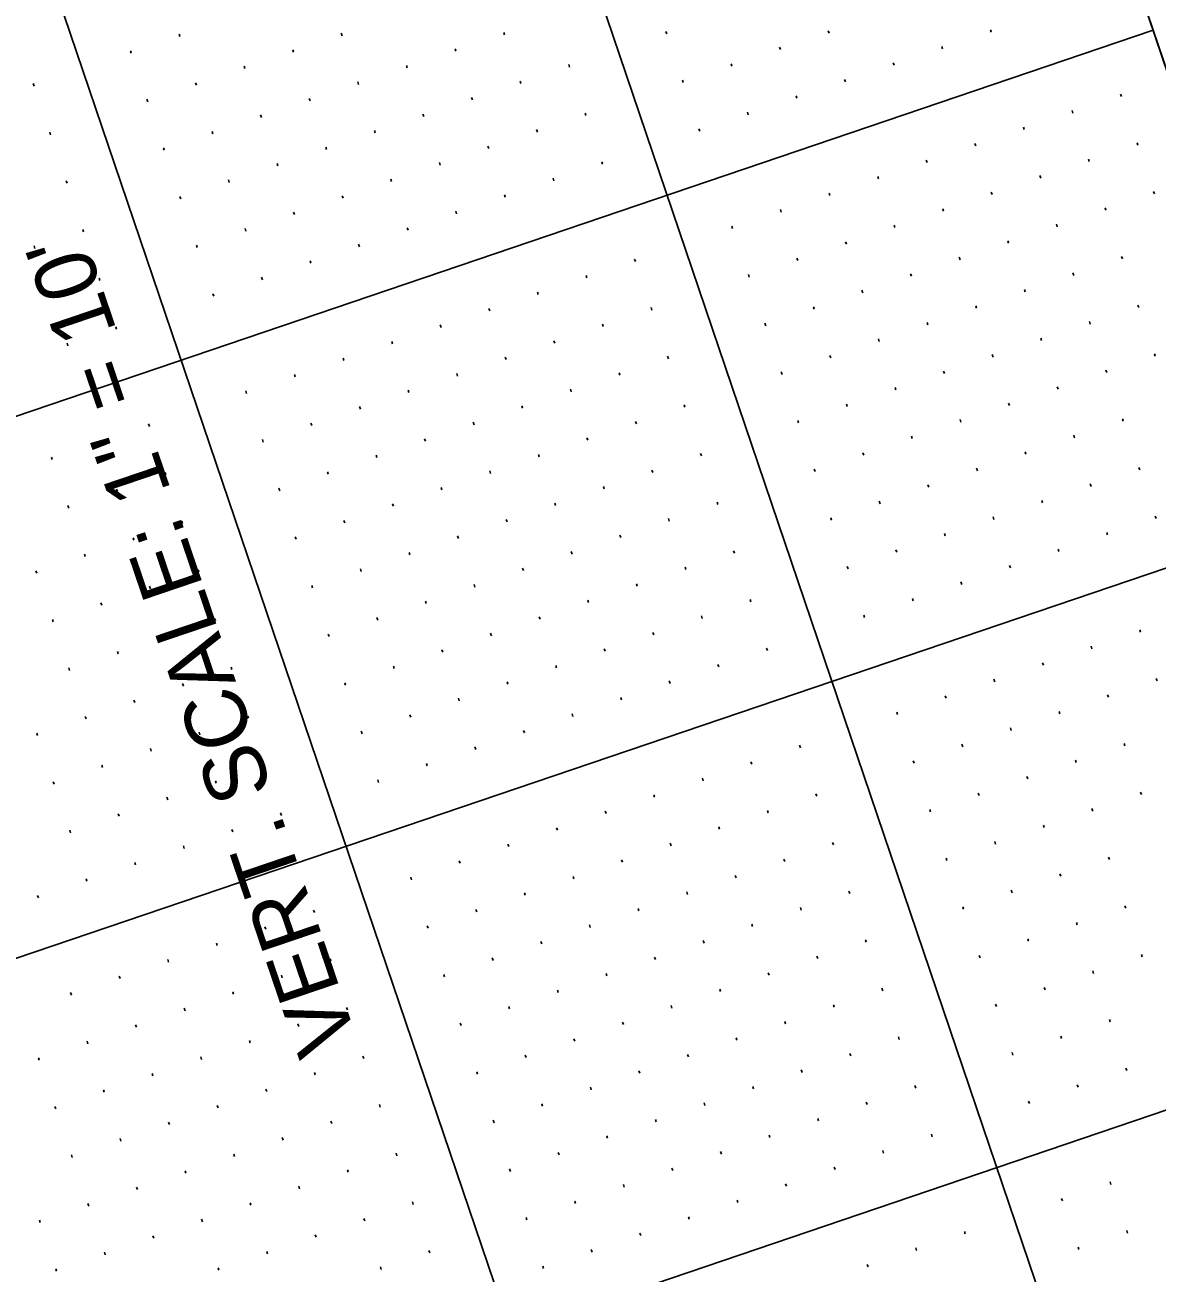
# Model space of a CAD drawing. Extents: x 2150800 to 2152547, y 141860 to 143950.
# Drawn here: x 2151679 to 2151789.3, y 143638.5 to 143760 of the extents above; entities that cross this region are included whole.
import ezdxf

# ---------------------------------------------------------------- set-up
doc = ezdxf.new("R2010")
doc.units = 0
for name, color, linetype in [('SHT_Profile_Grid_Major', 7, 'Continuous'), ('SHT_Profile_Grid_Minor', 7, 'Continuous'), ('SHT_Scale', 7, 'Continuous'), ('SHT_Sheet_Border', 7, 'Continuous')]:
    doc.layers.add(name, color=color, linetype=linetype)

msp = doc.modelspace()

# ---------------------------------------------------------------- linework, layer by layer
at = {"layer": 'SHT_Profile_Grid_Major'}
for p, q in [((2152266.81, 142350.86), (2151760.82, 143842.37)), ((2152219.46, 142334.8), (2151713.47, 143826.31)), ((2152172.11, 142318.73), (2151666.12, 143810.24)), ((2151788.93, 143759.51), (2151452.75, 143645.46)), ((2151804.99, 143712.16), (2151468.81, 143598.11)), ((2151892.08, 143688.9), (2151484.88, 143550.76))]:
    msp.add_line(p, q, dxfattribs=at)
at = {"layer": 'SHT_Profile_Grid_Minor'}
for p, q in [((2151694.1, 143758.88), (2151694.02, 143759.12)), ((2151709.91, 143758.97), (2151709.83, 143759.21)), ((2151725.73, 143759.05), (2151725.65, 143759.29)), ((2151741.54, 143759.14), (2151741.46, 143759.37)), ((2151757.35, 143759.22), (2151757.27, 143759.46)), ((2151773.16, 143759.3), (2151773.08, 143759.54)), ((2151752.61, 143757.61), (2151752.53, 143757.85)), ((2151768.42, 143757.7), (2151768.34, 143757.93)), ((2151689.37, 143757.28), (2151689.29, 143757.51)), ((2151705.18, 143757.36), (2151705.1, 143757.6)), ((2151720.99, 143757.45), (2151720.91, 143757.68)), ((2151700.44, 143755.76), (2151700.36, 143755.99)), ((2151716.26, 143755.84), (2151716.18, 143756.08)), ((2151732.07, 143755.92), (2151731.99, 143756.16)), ((2151747.88, 143756.01), (2151747.8, 143756.24)), ((2151763.69, 143756.09), (2151763.61, 143756.33)), ((2151679.9, 143754.07), (2151679.82, 143754.3)), ((2151695.71, 143754.15), (2151695.63, 143754.39)), ((2151711.52, 143754.23), (2151711.44, 143754.47)), ((2151727.33, 143754.32), (2151727.25, 143754.55)), ((2151743.14, 143754.4), (2151743.06, 143754.64)), ((2151758.95, 143754.49), (2151758.87, 143754.72)), ((2151754.22, 143752.88), (2151754.14, 143753.12)), ((2151785.84, 143753.05), (2151785.76, 143753.28)), ((2151690.98, 143752.54), (2151690.89, 143752.78)), ((2151706.79, 143752.63), (2151706.71, 143752.86)), ((2151722.6, 143752.71), (2151722.52, 143752.95)), ((2151702.05, 143751.02), (2151701.97, 143751.26)), ((2151717.86, 143751.1), (2151717.78, 143751.34)), ((2151733.67, 143751.19), (2151733.59, 143751.43)), ((2151749.48, 143751.27), (2151749.4, 143751.51)), ((2151781.11, 143751.44), (2151781.03, 143751.68)), ((2151681.51, 143749.33), (2151681.42, 143749.57)), ((2151697.32, 143749.41), (2151697.24, 143749.65)), ((2151713.13, 143749.5), (2151713.05, 143749.74)), ((2151728.94, 143749.58), (2151728.86, 143749.82)), ((2151744.75, 143749.67), (2151744.67, 143749.9)), ((2151776.37, 143749.83), (2151776.29, 143750.07)), ((2151708.39, 143747.89), (2151708.31, 143748.13)), ((2151724.2, 143747.98), (2151724.12, 143748.21)), ((2151771.64, 143748.23), (2151771.56, 143748.46)), ((2151787.45, 143748.31), (2151787.37, 143748.55)), ((2151692.58, 143747.81), (2151692.5, 143748.04)), ((2151782.71, 143746.71), (2151782.63, 143746.94)), ((2151703.66, 143746.29), (2151703.58, 143746.52)), ((2151719.47, 143746.37), (2151719.39, 143746.61)), ((2151735.28, 143746.45), (2151735.2, 143746.69)), ((2151766.9, 143746.62), (2151766.82, 143746.86)), ((2151683.11, 143744.6), (2151683.03, 143744.83)), ((2151698.92, 143744.68), (2151698.84, 143744.92)), ((2151714.73, 143744.76), (2151714.65, 143745)), ((2151730.54, 143744.85), (2151730.46, 143745.08)), ((2151762.17, 143745.02), (2151762.09, 143745.25)), ((2151777.98, 143745.1), (2151777.9, 143745.34)), ((2151694.19, 143743.07), (2151694.11, 143743.31)), ((2151710, 143743.16), (2151709.92, 143743.39)), ((2151725.81, 143743.24), (2151725.73, 143743.48)), ((2151757.43, 143743.41), (2151757.35, 143743.65)), ((2151773.24, 143743.49), (2151773.16, 143743.73)), ((2151789.05, 143743.58), (2151788.97, 143743.81)), ((2151752.7, 143741.8), (2151752.62, 143742.04)), ((2151768.51, 143741.89), (2151768.43, 143742.12)), ((2151784.32, 143741.97), (2151784.24, 143742.21)), ((2151705.26, 143741.55), (2151705.18, 143741.79)), ((2151721.07, 143741.63), (2151720.99, 143741.87)), ((2151684.72, 143739.86), (2151684.64, 143740.1)), ((2151700.53, 143739.94), (2151700.45, 143740.18)), ((2151716.34, 143740.03), (2151716.26, 143740.27)), ((2151747.96, 143740.2), (2151747.88, 143740.43)), ((2151763.77, 143740.28), (2151763.69, 143740.52)), ((2151779.58, 143740.36), (2151779.5, 143740.6)), ((2151679.98, 143738.25), (2151679.9, 143738.49)), ((2151695.79, 143738.34), (2151695.71, 143738.57)), ((2151711.61, 143738.42), (2151711.52, 143738.66)), ((2151759.04, 143738.67), (2151758.96, 143738.91)), ((2151774.85, 143738.76), (2151774.77, 143738.99)), ((2151738.49, 143736.98), (2151738.41, 143737.22)), ((2151754.3, 143737.07), (2151754.22, 143737.3)), ((2151770.11, 143737.15), (2151770.03, 143737.39)), ((2151785.93, 143737.24), (2151785.85, 143737.47)), ((2151706.87, 143736.82), (2151706.79, 143737.05)), ((2151686.32, 143735.13), (2151686.24, 143735.36)), ((2151702.14, 143735.21), (2151702.05, 143735.45)), ((2151733.76, 143735.38), (2151733.68, 143735.61)), ((2151749.57, 143735.46), (2151749.49, 143735.7)), ((2151765.38, 143735.55), (2151765.3, 143735.78)), ((2151781.19, 143735.63), (2151781.11, 143735.87)), ((2151681.59, 143733.52), (2151681.51, 143733.76)), ((2151697.4, 143733.6), (2151697.32, 143733.84)), ((2151729.02, 143733.77), (2151728.94, 143734.01)), ((2151760.64, 143733.94), (2151760.56, 143734.18)), ((2151776.46, 143734.02), (2151776.38, 143734.26)), ((2151724.29, 143732.16), (2151724.21, 143732.4)), ((2151740.1, 143732.25), (2151740.02, 143732.49)), ((2151755.91, 143732.33), (2151755.83, 143732.57)), ((2151771.72, 143732.42), (2151771.64, 143732.65)), ((2151787.53, 143732.5), (2151787.45, 143732.74)), ((2151782.8, 143730.89), (2151782.72, 143731.13)), ((2151687.93, 143730.39), (2151687.85, 143730.63)), ((2151719.55, 143730.56), (2151719.47, 143730.8)), ((2151735.36, 143730.64), (2151735.28, 143730.88)), ((2151751.18, 143730.73), (2151751.09, 143730.96)), ((2151766.99, 143730.81), (2151766.91, 143731.05)), ((2151683.2, 143728.78), (2151683.12, 143729.02)), ((2151714.82, 143728.95), (2151714.74, 143729.19)), ((2151730.63, 143729.04), (2151730.55, 143729.27)), ((2151762.25, 143729.2), (2151762.17, 143729.44)), ((2151778.06, 143729.29), (2151777.98, 143729.53)), ((2151710.08, 143727.35), (2151710, 143727.58)), ((2151725.89, 143727.43), (2151725.81, 143727.67)), ((2151741.71, 143727.51), (2151741.62, 143727.75)), ((2151757.52, 143727.6), (2151757.44, 143727.83)), ((2151773.33, 143727.68), (2151773.25, 143727.92)), ((2151789.14, 143727.77), (2151789.06, 143728)), ((2151752.78, 143725.99), (2151752.7, 143726.23)), ((2151768.59, 143726.08), (2151768.51, 143726.31)), ((2151784.4, 143726.16), (2151784.32, 143726.4)), ((2151705.35, 143725.74), (2151705.27, 143725.98)), ((2151721.16, 143725.82), (2151721.08, 143726.06)), ((2151736.97, 143725.91), (2151736.89, 143726.14)), ((2151700.61, 143724.13), (2151700.53, 143724.37)), ((2151716.42, 143724.22), (2151716.34, 143724.45)), ((2151732.24, 143724.3), (2151732.15, 143724.54)), ((2151763.86, 143724.47), (2151763.78, 143724.71)), ((2151779.67, 143724.55), (2151779.59, 143724.79)), ((2151711.69, 143722.61), (2151711.61, 143722.85)), ((2151727.5, 143722.7), (2151727.42, 143722.93)), ((2151743.31, 143722.78), (2151743.23, 143723.02)), ((2151759.12, 143722.86), (2151759.04, 143723.1)), ((2151774.93, 143722.95), (2151774.85, 143723.18)), ((2151738.58, 143721.17), (2151738.5, 143721.41)), ((2151754.39, 143721.26), (2151754.31, 143721.49)), ((2151770.2, 143721.34), (2151770.12, 143721.58)), ((2151786.01, 143721.42), (2151785.93, 143721.66)), ((2151691.14, 143720.92), (2151691.06, 143721.16)), ((2151706.95, 143721), (2151706.87, 143721.24)), ((2151722.77, 143721.09), (2151722.69, 143721.33)), ((2151686.41, 143719.31), (2151686.33, 143719.55)), ((2151702.22, 143719.4), (2151702.14, 143719.64)), ((2151718.03, 143719.48), (2151717.95, 143719.72)), ((2151733.84, 143719.57), (2151733.76, 143719.8)), ((2151765.46, 143719.73), (2151765.38, 143719.97)), ((2151781.28, 143719.82), (2151781.19, 143720.06)), ((2151681.67, 143717.71), (2151681.59, 143717.94)), ((2151713.3, 143717.88), (2151713.22, 143718.11)), ((2151729.11, 143717.96), (2151729.03, 143718.2)), ((2151744.92, 143718.04), (2151744.84, 143718.28)), ((2151760.73, 143718.13), (2151760.65, 143718.36)), ((2151776.54, 143718.21), (2151776.46, 143718.45)), ((2151708.56, 143716.27), (2151708.48, 143716.51)), ((2151724.37, 143716.35), (2151724.29, 143716.59)), ((2151740.18, 143716.44), (2151740.1, 143716.67)), ((2151755.99, 143716.52), (2151755.91, 143716.76)), ((2151771.81, 143716.61), (2151771.72, 143716.84)), ((2151787.62, 143716.69), (2151787.54, 143716.93)), ((2151692.75, 143716.19), (2151692.67, 143716.42)), ((2151782.88, 143715.08), (2151782.8, 143715.32)), ((2151688.01, 143714.58), (2151687.93, 143714.82)), ((2151703.83, 143714.66), (2151703.75, 143714.9)), ((2151719.64, 143714.75), (2151719.56, 143714.98)), ((2151735.45, 143714.83), (2151735.37, 143715.07)), ((2151767.07, 143715), (2151766.99, 143715.24)), ((2151683.28, 143712.97), (2151683.2, 143713.21)), ((2151714.9, 143713.14), (2151714.82, 143713.38)), ((2151730.71, 143713.23), (2151730.63, 143713.46)), ((2151746.52, 143713.31), (2151746.44, 143713.55)), ((2151762.34, 143713.39), (2151762.25, 143713.63)), ((2151778.15, 143713.48), (2151778.07, 143713.71)), ((2151694.36, 143711.45), (2151694.28, 143711.69)), ((2151710.17, 143711.53), (2151710.09, 143711.77)), ((2151725.98, 143711.62), (2151725.9, 143711.86)), ((2151741.79, 143711.7), (2151741.71, 143711.94)), ((2151757.6, 143711.79), (2151757.52, 143712.02)), ((2151773.41, 143711.87), (2151773.33, 143712.11)), ((2151789.22, 143711.95), (2151789.14, 143712.19)), ((2151768.68, 143710.26), (2151768.6, 143710.5)), ((2151784.49, 143710.35), (2151784.41, 143710.59)), ((2151689.62, 143709.84), (2151689.54, 143710.08)), ((2151705.43, 143709.93), (2151705.35, 143710.17)), ((2151721.24, 143710.01), (2151721.16, 143710.25)), ((2151737.05, 143710.1), (2151736.97, 143710.33)), ((2151684.89, 143708.24), (2151684.81, 143708.47)), ((2151716.51, 143708.41), (2151716.43, 143708.64)), ((2151732.32, 143708.49), (2151732.24, 143708.73)), ((2151748.13, 143708.57), (2151748.05, 143708.81)), ((2151763.94, 143708.66), (2151763.86, 143708.89)), ((2151779.75, 143708.74), (2151779.67, 143708.98)), ((2151680.15, 143706.63), (2151680.07, 143706.87)), ((2151695.96, 143706.72), (2151695.88, 143706.95)), ((2151711.77, 143706.8), (2151711.69, 143707.04)), ((2151727.58, 143706.88), (2151727.5, 143707.12)), ((2151743.4, 143706.97), (2151743.32, 143707.2)), ((2151759.21, 143707.05), (2151759.13, 143707.29)), ((2151775.02, 143707.14), (2151774.94, 143707.37)), ((2151738.66, 143705.36), (2151738.58, 143705.6)), ((2151770.28, 143705.53), (2151770.2, 143705.77)), ((2151691.23, 143705.11), (2151691.15, 143705.35)), ((2151707.04, 143705.19), (2151706.96, 143705.43)), ((2151722.85, 143705.28), (2151722.77, 143705.51)), ((2151686.49, 143703.5), (2151686.41, 143703.74)), ((2151718.11, 143703.67), (2151718.03, 143703.91)), ((2151733.93, 143703.76), (2151733.85, 143703.99)), ((2151749.74, 143703.84), (2151749.66, 143704.08)), ((2151765.55, 143703.92), (2151765.47, 143704.16)), ((2151681.76, 143701.9), (2151681.68, 143702.13)), ((2151697.57, 143701.98), (2151697.49, 143702.22)), ((2151713.38, 143702.06), (2151713.3, 143702.3)), ((2151729.19, 143702.15), (2151729.11, 143702.39)), ((2151745, 143702.23), (2151744.92, 143702.47)), ((2151760.81, 143702.32), (2151760.73, 143702.55)), ((2151708.64, 143700.46), (2151708.56, 143700.7)), ((2151724.46, 143700.54), (2151724.38, 143700.78)), ((2151740.27, 143700.63), (2151740.19, 143700.86)), ((2151787.7, 143700.88), (2151787.62, 143701.12)), ((2151692.83, 143700.37), (2151692.75, 143700.61)), ((2151782.97, 143699.27), (2151782.89, 143699.51)), ((2151688.1, 143698.77), (2151688.02, 143699.01)), ((2151719.72, 143698.94), (2151719.64, 143699.17)), ((2151735.53, 143699.02), (2151735.45, 143699.26)), ((2151751.34, 143699.1), (2151751.26, 143699.34)), ((2151683.36, 143697.16), (2151683.28, 143697.4)), ((2151699.17, 143697.25), (2151699.09, 143697.48)), ((2151714.99, 143697.33), (2151714.91, 143697.57)), ((2151730.8, 143697.41), (2151730.72, 143697.65)), ((2151746.61, 143697.5), (2151746.53, 143697.73)), ((2151778.23, 143697.67), (2151778.15, 143697.9)), ((2151694.44, 143695.64), (2151694.36, 143695.88)), ((2151710.25, 143695.72), (2151710.17, 143695.96)), ((2151726.06, 143695.81), (2151725.98, 143696.04)), ((2151741.87, 143695.89), (2151741.79, 143696.13)), ((2151773.5, 143696.06), (2151773.42, 143696.3)), ((2151789.31, 143696.14), (2151789.23, 143696.38)), ((2151768.76, 143694.45), (2151768.68, 143694.69)), ((2151784.57, 143694.54), (2151784.49, 143694.77)), ((2151689.7, 143694.03), (2151689.62, 143694.27)), ((2151721.33, 143694.2), (2151721.25, 143694.44)), ((2151737.14, 143694.29), (2151737.06, 143694.52)), ((2151684.97, 143692.43), (2151684.89, 143692.66)), ((2151700.78, 143692.51), (2151700.7, 143692.75)), ((2151716.59, 143692.6), (2151716.51, 143692.83)), ((2151732.4, 143692.68), (2151732.32, 143692.92)), ((2151764.03, 143692.85), (2151763.95, 143693.08)), ((2151779.84, 143692.93), (2151779.76, 143693.17)), ((2151680.23, 143690.82), (2151680.15, 143691.06)), ((2151696.05, 143690.9), (2151695.97, 143691.14)), ((2151711.86, 143690.99), (2151711.78, 143691.23)), ((2151727.67, 143691.07), (2151727.59, 143691.31)), ((2151775.1, 143691.32), (2151775.02, 143691.56)), ((2151754.56, 143689.63), (2151754.48, 143689.87)), ((2151770.37, 143689.72), (2151770.29, 143689.96)), ((2151786.18, 143689.8), (2151786.1, 143690.04)), ((2151691.31, 143689.3), (2151691.23, 143689.54)), ((2151722.93, 143689.47), (2151722.85, 143689.7)), ((2151686.58, 143687.69), (2151686.5, 143687.93)), ((2151702.39, 143687.78), (2151702.31, 143688.01)), ((2151718.2, 143687.86), (2151718.12, 143688.1)), ((2151749.82, 143688.03), (2151749.74, 143688.26)), ((2151765.63, 143688.11), (2151765.55, 143688.35)), ((2151781.44, 143688.2), (2151781.36, 143688.43)), ((2151681.84, 143686.09), (2151681.76, 143686.32)), ((2151697.65, 143686.17), (2151697.57, 143686.41)), ((2151713.46, 143686.25), (2151713.38, 143686.49)), ((2151745.09, 143686.42), (2151745.01, 143686.66)), ((2151776.71, 143686.59), (2151776.63, 143686.83)), ((2151740.35, 143684.82), (2151740.27, 143685.05)), ((2151756.16, 143684.9), (2151756.08, 143685.14)), ((2151771.97, 143684.98), (2151771.89, 143685.22)), ((2151787.78, 143685.07), (2151787.7, 143685.3)), ((2151692.92, 143684.56), (2151692.84, 143684.8)), ((2151783.05, 143683.46), (2151782.97, 143683.7)), ((2151688.18, 143682.96), (2151688.1, 143683.19)), ((2151703.99, 143683.04), (2151703.91, 143683.28)), ((2151735.62, 143683.21), (2151735.54, 143683.45)), ((2151751.43, 143683.29), (2151751.35, 143683.53)), ((2151767.24, 143683.38), (2151767.16, 143683.61)), ((2151683.45, 143681.35), (2151683.37, 143681.59)), ((2151699.26, 143681.43), (2151699.18, 143681.67)), ((2151730.88, 143681.6), (2151730.8, 143681.84)), ((2151746.69, 143681.69), (2151746.61, 143681.92)), ((2151778.31, 143681.85), (2151778.23, 143682.09)), ((2151694.52, 143679.83), (2151694.44, 143680.07)), ((2151726.15, 143680), (2151726.07, 143680.23)), ((2151741.96, 143680.08), (2151741.88, 143680.32)), ((2151757.77, 143680.16), (2151757.69, 143680.4)), ((2151773.58, 143680.25), (2151773.5, 143680.49)), ((2151768.84, 143678.64), (2151768.76, 143678.88)), ((2151784.66, 143678.73), (2151784.58, 143678.96)), ((2151689.79, 143678.22), (2151689.71, 143678.46)), ((2151721.41, 143678.39), (2151721.33, 143678.63)), ((2151737.22, 143678.47), (2151737.14, 143678.71)), ((2151753.03, 143678.56), (2151752.95, 143678.79)), ((2151685.05, 143676.62), (2151684.97, 143676.85)), ((2151716.68, 143676.78), (2151716.6, 143677.02)), ((2151732.49, 143676.87), (2151732.41, 143677.1)), ((2151748.3, 143676.95), (2151748.22, 143677.19)), ((2151779.92, 143677.12), (2151779.84, 143677.36)), ((2151680.32, 143675.01), (2151680.24, 143675.25)), ((2151727.75, 143675.26), (2151727.67, 143675.5)), ((2151743.56, 143675.35), (2151743.48, 143675.58)), ((2151759.37, 143675.43), (2151759.29, 143675.67)), ((2151775.19, 143675.51), (2151775.11, 143675.75)), ((2151738.83, 143673.74), (2151738.75, 143673.98)), ((2151754.64, 143673.82), (2151754.56, 143674.06)), ((2151770.45, 143673.91), (2151770.37, 143674.14)), ((2151786.26, 143673.99), (2151786.18, 143674.23)), ((2151707.21, 143673.57), (2151707.13, 143673.81)), ((2151723.02, 143673.66), (2151722.94, 143673.89)), ((2151702.47, 143671.96), (2151702.39, 143672.2)), ((2151718.28, 143672.05), (2151718.2, 143672.29)), ((2151734.09, 143672.13), (2151734.01, 143672.37)), ((2151749.9, 143672.22), (2151749.82, 143672.45)), ((2151781.53, 143672.38), (2151781.45, 143672.62)), ((2151697.74, 143670.36), (2151697.66, 143670.6)), ((2151729.36, 143670.53), (2151729.28, 143670.76)), ((2151745.17, 143670.61), (2151745.09, 143670.85)), ((2151760.98, 143670.69), (2151760.9, 143670.93)), ((2151776.79, 143670.78), (2151776.71, 143671.02)), ((2151724.62, 143668.92), (2151724.54, 143669.16)), ((2151740.43, 143669), (2151740.35, 143669.24)), ((2151756.25, 143669.09), (2151756.17, 143669.33)), ((2151772.06, 143669.17), (2151771.98, 143669.41)), ((2151787.87, 143669.26), (2151787.79, 143669.49)), ((2151693, 143668.75), (2151692.92, 143668.99)), ((2151708.81, 143668.84), (2151708.73, 143669.07)), ((2151783.13, 143667.65), (2151783.05, 143667.89)), ((2151688.27, 143667.15), (2151688.19, 143667.38)), ((2151704.08, 143667.23), (2151704, 143667.47)), ((2151719.89, 143667.31), (2151719.81, 143667.55)), ((2151735.7, 143667.4), (2151735.62, 143667.63)), ((2151751.51, 143667.48), (2151751.43, 143667.72)), ((2151683.53, 143665.54), (2151683.45, 143665.78)), ((2151699.34, 143665.62), (2151699.26, 143665.86)), ((2151730.96, 143665.79), (2151730.88, 143666.03)), ((2151746.78, 143665.88), (2151746.7, 143666.11)), ((2151762.59, 143665.96), (2151762.51, 143666.2)), ((2151778.4, 143666.04), (2151778.32, 143666.28)), ((2151694.61, 143664.02), (2151694.53, 143664.25)), ((2151710.42, 143664.1), (2151710.34, 143664.34)), ((2151726.23, 143664.19), (2151726.15, 143664.42)), ((2151742.04, 143664.27), (2151741.96, 143664.51)), ((2151757.85, 143664.35), (2151757.77, 143664.59)), ((2151773.66, 143664.44), (2151773.58, 143664.67)), ((2151784.74, 143662.92), (2151784.66, 143663.15)), ((2151689.87, 143662.41), (2151689.79, 143662.65)), ((2151705.68, 143662.49), (2151705.6, 143662.73)), ((2151721.5, 143662.58), (2151721.41, 143662.82)), ((2151737.31, 143662.66), (2151737.23, 143662.9)), ((2151753.12, 143662.75), (2151753.04, 143662.98)), ((2151685.14, 143660.8), (2151685.06, 143661.04)), ((2151700.95, 143660.89), (2151700.87, 143661.13)), ((2151732.57, 143661.06), (2151732.49, 143661.29)), ((2151748.38, 143661.14), (2151748.3, 143661.38)), ((2151764.19, 143661.22), (2151764.11, 143661.46)), ((2151780, 143661.31), (2151779.92, 143661.55)), ((2151680.4, 143659.2), (2151680.32, 143659.44)), ((2151696.21, 143659.28), (2151696.13, 143659.52)), ((2151712.03, 143659.37), (2151711.94, 143659.6)), ((2151727.84, 143659.45), (2151727.76, 143659.69)), ((2151743.65, 143659.53), (2151743.57, 143659.77)), ((2151759.46, 143659.62), (2151759.38, 143659.86)), ((2151775.27, 143659.7), (2151775.19, 143659.94)), ((2151738.91, 143657.93), (2151738.83, 143658.16)), ((2151754.72, 143658.01), (2151754.64, 143658.25)), ((2151786.35, 143658.18), (2151786.27, 143658.42)), ((2151691.48, 143657.68), (2151691.4, 143657.91)), ((2151707.29, 143657.76), (2151707.21, 143658)), ((2151723.1, 143657.84), (2151723.02, 143658.08)), ((2151686.74, 143656.07), (2151686.66, 143656.31)), ((2151702.56, 143656.15), (2151702.47, 143656.39)), ((2151734.18, 143656.32), (2151734.1, 143656.56)), ((2151749.99, 143656.41), (2151749.91, 143656.64)), ((2151765.8, 143656.49), (2151765.72, 143656.73)), ((2151781.61, 143656.57), (2151781.53, 143656.81)), ((2151682.01, 143654.46), (2151681.93, 143654.7)), ((2151697.82, 143654.55), (2151697.74, 143654.78)), ((2151713.63, 143654.63), (2151713.55, 143654.87)), ((2151729.44, 143654.72), (2151729.36, 143654.95)), ((2151745.25, 143654.8), (2151745.17, 143655.04)), ((2151761.06, 143654.88), (2151760.98, 143655.12)), ((2151776.88, 143654.97), (2151776.8, 143655.2)), ((2151724.71, 143653.11), (2151724.63, 143653.35)), ((2151740.52, 143653.19), (2151740.44, 143653.43)), ((2151756.33, 143653.28), (2151756.25, 143653.51)), ((2151693.09, 143652.94), (2151693, 143653.18)), ((2151708.9, 143653.03), (2151708.82, 143653.26)), ((2151688.35, 143651.33), (2151688.27, 143651.57)), ((2151704.16, 143651.42), (2151704.08, 143651.66)), ((2151735.78, 143651.59), (2151735.7, 143651.82)), ((2151751.59, 143651.67), (2151751.51, 143651.91)), ((2151767.41, 143651.75), (2151767.33, 143651.99)), ((2151683.62, 143649.73), (2151683.54, 143649.97)), ((2151699.43, 143649.81), (2151699.35, 143650.05)), ((2151715.24, 143649.9), (2151715.16, 143650.13)), ((2151731.05, 143649.98), (2151730.97, 143650.22)), ((2151746.86, 143650.06), (2151746.78, 143650.3)), ((2151762.67, 143650.15), (2151762.59, 143650.39)), ((2151694.69, 143648.21), (2151694.61, 143648.44)), ((2151710.5, 143648.29), (2151710.42, 143648.53)), ((2151726.31, 143648.37), (2151726.23, 143648.61)), ((2151742.13, 143648.46), (2151742.04, 143648.69)), ((2151757.94, 143648.54), (2151757.86, 143648.78)), ((2151784.82, 143647.1), (2151784.74, 143647.34)), ((2151689.96, 143646.6), (2151689.88, 143646.84)), ((2151705.77, 143646.68), (2151705.69, 143646.92)), ((2151737.39, 143646.85), (2151737.31, 143647.09)), ((2151753.2, 143646.94), (2151753.12, 143647.17)), ((2151685.22, 143644.99), (2151685.14, 143645.23)), ((2151701.03, 143645.08), (2151700.95, 143645.31)), ((2151716.84, 143645.16), (2151716.76, 143645.4)), ((2151732.66, 143645.25), (2151732.57, 143645.48)), ((2151748.47, 143645.33), (2151748.39, 143645.57)), ((2151780.09, 143645.5), (2151780.01, 143645.73)), ((2151680.49, 143643.39), (2151680.41, 143643.62)), ((2151696.3, 143643.47), (2151696.22, 143643.71)), ((2151712.11, 143643.56), (2151712.03, 143643.79)), ((2151727.92, 143643.64), (2151727.84, 143643.88)), ((2151743.73, 143643.72), (2151743.65, 143643.96)), ((2151739, 143642.12), (2151738.92, 143642.35)), ((2151770.62, 143642.28), (2151770.54, 143642.52)), ((2151786.43, 143642.37), (2151786.35, 143642.61)), ((2151691.56, 143641.86), (2151691.48, 143642.1)), ((2151707.37, 143641.95), (2151707.29, 143642.19)), ((2151686.83, 143640.26), (2151686.75, 143640.5)), ((2151702.64, 143640.34), (2151702.56, 143640.58)), ((2151718.45, 143640.43), (2151718.37, 143640.66)), ((2151734.26, 143640.51), (2151734.18, 143640.75)), ((2151765.88, 143640.68), (2151765.8, 143640.92)), ((2151781.7, 143640.76), (2151781.61, 143641)), ((2151682.09, 143638.65), (2151682.01, 143638.89)), ((2151697.9, 143638.74), (2151697.82, 143638.97)), ((2151713.72, 143638.82), (2151713.64, 143639.06)), ((2151729.53, 143638.9), (2151729.45, 143639.14)), ((2151761.15, 143639.07), (2151761.07, 143639.31))]:
    msp.add_line(p, q, dxfattribs=at)
at = {"layer": 'SHT_Sheet_Border'}
msp.add_lwpolyline([(2151821.06, 143664.81), (2151840, 143671.23), (2151791.81, 143813.28), (2151772.87, 143806.86)], close=True, dxfattribs=at)

# ---------------------------------------------------------------- texts
at = {"layer": 'SHT_Scale'}
msp.add_text('VERT. SCALE: 1" = 10\'', height=6, rotation=108.7393, dxfattribs=at).set_placement((2151711.47, 143661))

doc.saveas('drawing.dxf')
